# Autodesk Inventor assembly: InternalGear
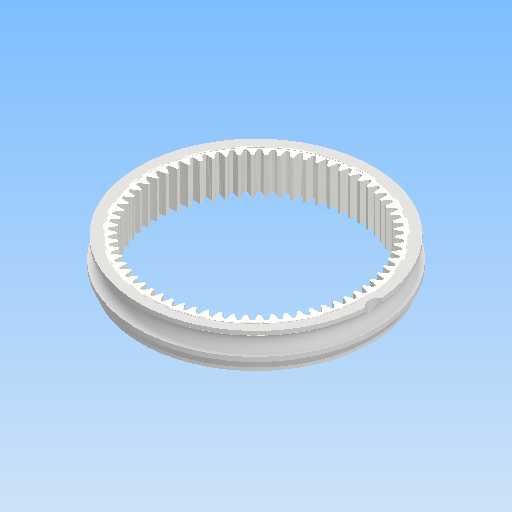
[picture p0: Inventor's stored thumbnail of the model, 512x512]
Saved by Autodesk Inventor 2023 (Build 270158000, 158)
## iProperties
Created: 2024-05
Part Number: InternalGear
Document SubType Name: Assembly
Designer: kumagai
Author: kumagai
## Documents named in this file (3)
- \\192.168.3.8\kumagai\Develop\CAD\NakataOmni\DriveUnitR3\InternalGear.iam
- \\192.168.3.8\kumagai\Develop\CAD\NakataOmni\DriveUnitR3\InternalGearRace.ipt
- \\192.168.3.8\kumagai\Develop\CAD\NakataOmni\DriveUnitR3\InternalGear_m1_66_Gear.ipt
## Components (2 placed, 2 different names)
1. InternalGearRace:1 — フラッシュ:1, フラッシュ:2, フラッシュ:3
2. 平歯車2:1 — フラッシュ:1, フラッシュ:2, フラッシュ:3
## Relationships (3: Flush 3)
- フラッシュ:1 [Flush]: InternalGearRace:1 ↔ 平歯車2:1
- フラッシュ:2 [Flush]: InternalGearRace:1 ↔ 平歯車2:1
- フラッシュ:3 [Flush]: InternalGearRace:1 ↔ 平歯車2:1
